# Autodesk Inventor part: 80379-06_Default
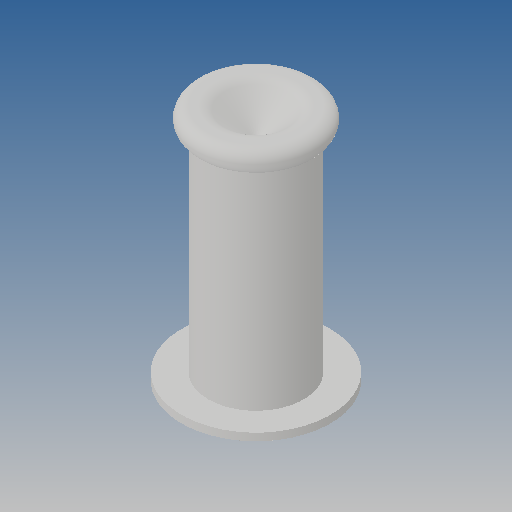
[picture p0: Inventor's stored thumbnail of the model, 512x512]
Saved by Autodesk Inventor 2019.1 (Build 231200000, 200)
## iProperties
Created: 2012-10
Part Number: 80379-06_Default
Material: Ogólny
Document SubType Name: Modeling
Designer: CADENGINEERING4
Density: 1 g/cm^3
Appearance: Domyślna
Author: CADENGINEERING4
Revision Number: ÈÎºÎ
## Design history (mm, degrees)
feature "Ðý×ª1"
node "Bryła1"
